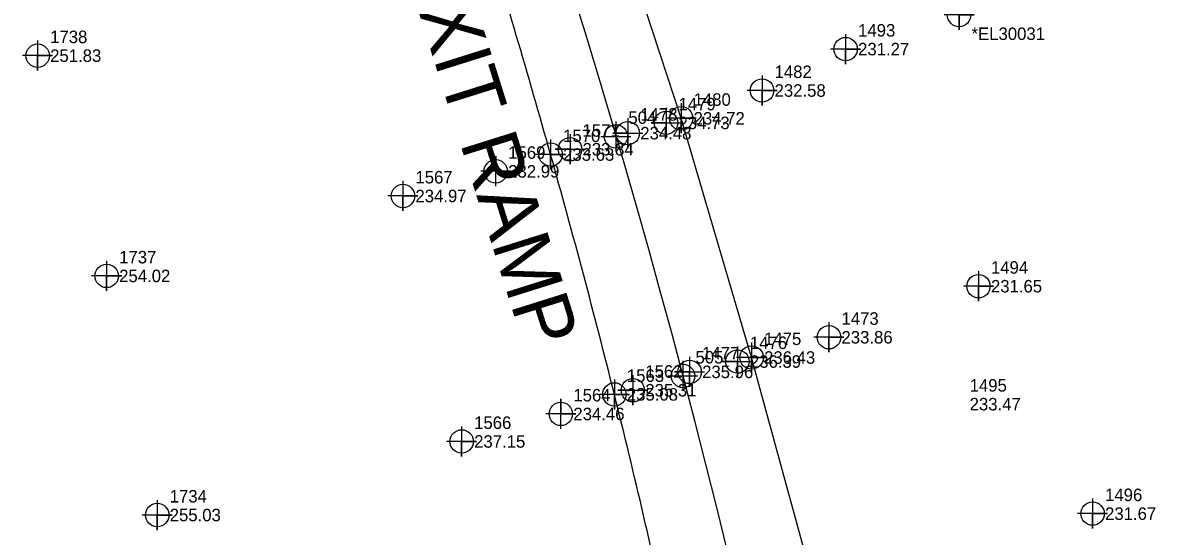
# Model space of a CAD drawing. Extents: x 2130621 to 2131998, y 642516 to 644503.
# Drawn here: x 2131046.3 to 2131272.8, y 643731.5 to 643834.2 of the extents above; entities that cross this region are included whole.
import ezdxf

# ---------------------------------------------------------------- set-up
doc = ezdxf.new("R2010")
doc.units = 0
for name, color, linetype in [('Cogo Default Point CELL', 7, 'Continuous'), ('COGO Default Point Number', 7, 'Continuous'), ('Exist Other Culture Area Outline Cogo Elevation', 7, 'Continuous'), ('Exist Other Culture Area Outline Cogo Number', 7, 'Continuous'), ('Exist Other Culture Area Outline Cogo Point CELL', 7, 'Continuous'), ('Exist Other Culture Fence Line Cogo Elevation', 7, 'Continuous'), ('Exist Other Culture Fence Line Cogo Number', 7, 'Continuous'), ('Exist Other Culture Fence Line Cogo Point CELL', 7, 'Continuous'), ('Exist Roads EOP', 7, 'Continuous'), ('Exist Roads EOP Cogo Elevation', 7, 'Continuous'), ('Exist Roads EOP Cogo Number', 7, 'Continuous'), ('Exist Roads EOP Cogo Point CELL', 7, 'Continuous'), ('Exist Roads EOP Other Cogo Comment', 7, 'Continuous'), ('Exist Roads EOP Other Cogo Point CELL', 7, 'Continuous'), ('Exist Roads EOT Cogo Elevation', 7, 'Continuous'), ('Exist Roads EOT Cogo Number', 7, 'Continuous'), ('Exist Roads EOT Cogo Point CELL', 7, 'Continuous'), ('Exist Roads EOT Text', 7, 'Continuous'), ('Exist Roads Soil Cogo Elevation', 7, 'Continuous'), ('Exist Roads Soil Cogo Number', 7, 'Continuous'), ('Exist Roads Soil Cogo Point CELL', 7, 'Continuous'), ('Exist Vegetation Tree Cogo Elevation', 7, 'Continuous'), ('Exist Vegetation Tree Cogo Number', 7, 'Continuous'), ('Exist Vegetation Woods Line Cogo Elevation', 7, 'Continuous'), ('Exist Vegetation Woods Line Cogo Number', 7, 'Continuous'), ('Exist Vegetation Woods Line Cogo Point CELL', 7, 'Continuous'), ('Prop Horizontal Alignment', 7, 'Continuous')]:
    doc.layers.add(name, color=color, linetype=linetype)

msp = doc.modelspace()

# ---------------------------------------------------------------- linework, layer by layer
at = {"layer": 'Cogo Default Point CELL'}
for points in [[(2131164.92, 643814.47), (2131164.92, 643811.47)], [(2131161.92, 643811.47), (2131164.92, 643811.47)], [(2131164.92, 643811.47), (2131167.92, 643811.47)], [(2131164.92, 643811.47), (2131164.92, 643808.47)], [(2131178.34, 643766.57), (2131178.34, 643763.57)], [(2131175.34, 643763.57), (2131178.34, 643763.57)], [(2131178.34, 643763.57), (2131181.34, 643763.57)], [(2131178.34, 643763.57), (2131178.34, 643760.57)]]:
    msp.add_lwpolyline(points, dxfattribs=at)
for centre in [(2131164.92, 643811.47), (2131178.34, 643763.57)]:
    msp.add_circle(centre, 2.34, dxfattribs=at)
at = {"layer": 'Exist Other Culture Area Outline Cogo Point CELL'}
for points in [[(2131210.86, 643831.93), (2131210.86, 643825.93), (2131210.86, 643828.93), (2131213.86, 643828.93), (2131207.86, 643828.93)], [(2131194.16, 643823.65), (2131194.16, 643817.65), (2131194.16, 643820.65), (2131197.16, 643820.65), (2131191.16, 643820.65)], [(2131237.43, 643784.52), (2131237.43, 643778.52), (2131237.43, 643781.52), (2131240.43, 643781.52), (2131234.43, 643781.52)], [(2131207.54, 643774.31), (2131207.54, 643768.31), (2131207.54, 643771.31), (2131210.54, 643771.31), (2131204.54, 643771.31)], [(2131260.25, 643739.05), (2131260.25, 643733.05), (2131260.25, 643736.05), (2131263.25, 643736.05), (2131257.25, 643736.05)]]:
    msp.add_lwpolyline(points, dxfattribs=at)
for centre in [(2131210.86, 643828.93), (2131194.16, 643820.65), (2131237.43, 643781.52), (2131207.54, 643771.31), (2131260.25, 643736.05)]:
    msp.add_circle(centre, 2.34, dxfattribs=at)
at = {"layer": 'Exist Other Culture Fence Line Cogo Point CELL'}
for points in [[(2131049.29, 643830.62), (2131049.29, 643824.62), (2131049.29, 643827.62), (2131052.29, 643827.62), (2131046.29, 643827.62)], [(2131063.09, 643786.58), (2131063.09, 643780.58), (2131063.09, 643783.58), (2131066.09, 643783.58), (2131060.09, 643783.58)], [(2131073.2, 643738.77), (2131073.2, 643732.77), (2131073.2, 643735.77), (2131076.2, 643735.77), (2131070.2, 643735.77)]]:
    msp.add_lwpolyline(points, dxfattribs=at)
for centre in [(2131049.29, 643827.62), (2131063.09, 643783.58), (2131073.2, 643735.77)]:
    msp.add_circle(centre, 2.34, dxfattribs=at)
at = {"layer": 'Exist Roads EOP'}
msp.add_lwpolyline([(2131264.27, 643222.56), (2131259.88, 643269.33), (2131257.02, 643319.4), (2131254.26, 643369.65), (2131250.08, 643419.42), (2131246.15, 643469.03), (2131240.84, 643519.13), (2131234.37, 643568.56), (2131226.33, 643620.18), (2131217.03, 643668.71), (2131205.62, 643717.61), (2131192.06, 643767.26), (2131177.97, 643815.09), (2131162.29, 643862.93), (2131145.36, 643910.85), (2131126.91, 643957.29), (2131112.37, 643996.12)], dxfattribs=at)
msp.add_spline([(2131166.25, 643216.7), (2131171.81, 643218.72), (2131182.37, 643223.97), (2131191.81, 643231.15), (2131200.5, 643239.7), (2131208.81, 643249.07), (2131216.07, 643259), (2131218.72, 643264.35), (2131220.54, 643270.1), (2131222.84, 643282.01), (2131224.36, 643293.92), (2131224.88, 643317.79), (2131222.06, 643367.67), (2131218.54, 643416.81), (2131214.32, 643466.35), (2131209.17, 643515.67), (2131202.79, 643565.15), (2131195.05, 643613.99), (2131186.4, 643662.48), (2131176.01, 643711.41), (2131164.62, 643759.89), (2131151.87, 643807.85), (2131137.86, 643855.41), (2131122.57, 643902.86), (2131105.96, 643949.49), (2131091.53, 643988.04)], degree=3, dxfattribs=at)
at = {"layer": 'Exist Roads EOP Cogo Point CELL'}
for points in [[(2131177.97, 643818.09), (2131177.97, 643812.09), (2131177.97, 643815.09), (2131180.97, 643815.09), (2131174.97, 643815.09)], [(2131151.87, 643810.85), (2131151.87, 643804.85), (2131151.87, 643807.85), (2131154.87, 643807.85), (2131148.87, 643807.85)], [(2131192.06, 643770.26), (2131192.06, 643764.26), (2131192.06, 643767.26), (2131195.06, 643767.26), (2131189.06, 643767.26)], [(2131164.62, 643762.89), (2131164.62, 643756.89), (2131164.62, 643759.89), (2131167.62, 643759.89), (2131161.62, 643759.89)]]:
    msp.add_lwpolyline(points, dxfattribs=at)
for centre in [(2131177.97, 643815.09), (2131151.87, 643807.85), (2131192.06, 643767.26), (2131164.62, 643759.89)]:
    msp.add_circle(centre, 2.34, dxfattribs=at)
at = {"layer": 'Exist Roads EOP Other Cogo Point CELL'}
msp.add_lwpolyline([(2131233.55, 643838.75), (2131233.55, 643832.75), (2131233.55, 643835.75), (2131236.55, 643835.75), (2131230.55, 643835.75)], dxfattribs=at)
msp.add_circle((2131233.55, 643835.75), 2.34, dxfattribs=at)
at = {"layer": 'Exist Roads EOT Cogo Point CELL'}
for points in [[(2131167.3, 643815.12), (2131167.3, 643809.12), (2131167.3, 643812.12), (2131164.3, 643812.12), (2131170.3, 643812.12)], [(2131174.95, 643817.18), (2131174.95, 643811.18), (2131174.95, 643814.18), (2131171.95, 643814.18), (2131177.95, 643814.18)], [(2131155.75, 643811.91), (2131155.75, 643805.91), (2131155.75, 643808.91), (2131152.75, 643808.91), (2131158.75, 643808.91)], [(2131189.23, 643769.46), (2131189.23, 643763.46), (2131189.23, 643766.46), (2131186.23, 643766.46), (2131192.23, 643766.46)], [(2131179.67, 643767.39), (2131179.67, 643761.39), (2131179.67, 643764.39), (2131176.67, 643764.39), (2131182.67, 643764.39)], [(2131168.31, 643763.72), (2131168.31, 643757.72), (2131168.31, 643760.72), (2131165.31, 643760.72), (2131171.31, 643760.72)]]:
    msp.add_lwpolyline(points, dxfattribs=at)
for centre in [(2131174.95, 643814.18), (2131167.3, 643812.12), (2131155.75, 643808.91), (2131189.23, 643766.46), (2131179.67, 643764.39), (2131168.31, 643760.72)]:
    msp.add_circle(centre, 2.34, dxfattribs=at)
at = {"layer": 'Exist Roads Soil Cogo Point CELL'}
for points in [[(2131140.89, 643801.49), (2131140.89, 643807.49), (2131140.89, 643804.49), (2131143.89, 643804.49), (2131137.89, 643804.49)], [(2131153.92, 643752.98), (2131153.92, 643758.98), (2131153.92, 643755.98), (2131156.92, 643755.98), (2131150.92, 643755.98)]]:
    msp.add_lwpolyline(points, dxfattribs=at)
for centre in [(2131140.89, 643804.49), (2131153.92, 643755.98)]:
    msp.add_circle(centre, 2.34, dxfattribs=at)
at = {"layer": 'Exist Vegetation Woods Line Cogo Point CELL'}
for points in [[(2131122.34, 643802.56), (2131122.34, 643796.56), (2131122.34, 643799.56), (2131125.34, 643799.56), (2131119.34, 643799.56)], [(2131134.08, 643753.48), (2131134.08, 643747.48), (2131134.08, 643750.48), (2131137.08, 643750.48), (2131131.08, 643750.48)]]:
    msp.add_lwpolyline(points, dxfattribs=at)
for centre in [(2131122.34, 643799.56), (2131134.08, 643750.48)]:
    msp.add_circle(centre, 2.34, dxfattribs=at)
at = {"layer": 'Prop Horizontal Alignment'}
msp.add_arc((2129448.47, 643307.66), 1788.96, 4.14306, 22.49968, dxfattribs=at)

# ---------------------------------------------------------------- texts
at = {"layer": 'COGO Default Point Number'}
for s, p in [('504', (2131167.42, 643813.97)), ('505', (2131180.84, 643766.07))]:
    msp.add_text(s, height=2.5, dxfattribs=at).set_placement(p)
at = {"layer": 'Exist Other Culture Area Outline Cogo Elevation'}
for s, p in [('231.27', (2131213.36, 643827.68)), ('232.58', (2131196.66, 643819.4)), ('231.65', (2131239.93, 643780.27)), ('233.86', (2131210.04, 643770.06)), ('231.67', (2131262.75, 643734.8))]:
    msp.add_text(s, height=2.5, dxfattribs=at).set_placement(p)
at = {"layer": 'Exist Other Culture Area Outline Cogo Number'}
for s, p in [('1493', (2131213.36, 643831.43)), ('1482', (2131196.66, 643823.15)), ('1494', (2131239.93, 643784.02)), ('1473', (2131210.04, 643773.81)), ('1496', (2131262.75, 643738.55))]:
    msp.add_text(s, height=2.5, dxfattribs=at).set_placement(p)
at = {"layer": 'Exist Other Culture Fence Line Cogo Elevation'}
for s, p in [('251.83', (2131051.79, 643826.37)), ('254.02', (2131065.59, 643782.33)), ('255.03', (2131075.7, 643734.52))]:
    msp.add_text(s, height=2.5, dxfattribs=at).set_placement(p)
at = {"layer": 'Exist Other Culture Fence Line Cogo Number'}
for s, p in [('1738', (2131051.79, 643830.12)), ('1737', (2131065.59, 643786.08)), ('1734', (2131075.7, 643738.27))]:
    msp.add_text(s, height=2.5, dxfattribs=at).set_placement(p)
at = {"layer": 'Exist Roads EOP Cogo Elevation'}
for s, p in [('234.72', (2131180.47, 643813.84)), ('233.63', (2131154.37, 643806.6)), ('236.43', (2131194.56, 643766.01)), ('235.08', (2131167.12, 643758.64))]:
    msp.add_text(s, height=2.5, dxfattribs=at).set_placement(p)
at = {"layer": 'Exist Roads EOP Cogo Number'}
for s, p in [('1480', (2131180.47, 643817.59)), ('1570', (2131154.37, 643810.35)), ('1475', (2131194.56, 643769.76)), ('1563', (2131167.12, 643762.39))]:
    msp.add_text(s, height=2.5, dxfattribs=at).set_placement(p)
at = {"layer": 'Exist Roads EOP Other Cogo Comment'}
msp.add_text('*EL30031', height=2.5, dxfattribs=at).set_placement((2131236.05, 643830.75))
at = {"layer": 'Exist Roads EOT Cogo Elevation'}
for s, p in [('234.73', (2131177.45, 643812.93)), ('234.48', (2131169.8, 643810.87)), ('233.84', (2131158.25, 643807.66)), ('236.39', (2131191.73, 643765.21)), ('235.96', (2131182.17, 643763.14)), ('235.31', (2131170.81, 643759.47))]:
    msp.add_text(s, height=2.5, dxfattribs=at).set_placement(p)
at = {"layer": 'Exist Roads EOT Cogo Number'}
for s, p in [('1479', (2131177.45, 643816.68)), ('1478', (2131169.8, 643814.62)), ('1571', (2131158.25, 643811.41)), ('1476', (2131191.73, 643768.96)), ('1477', (2131182.17, 643766.89)), ('1562', (2131170.81, 643763.22))]:
    msp.add_text(s, height=2.5, dxfattribs=at).set_placement(p)
at = {"layer": 'Exist Roads EOT Text'}
msp.add_text('I-40 EAST BOUND EXIT RAMP', height=11.3735, rotation=287.4395, dxfattribs=at).set_placement((2131082.27, 643973.9))
at = {"layer": 'Exist Roads Soil Cogo Elevation'}
for s, p in [('232.99', (2131143.39, 643803.24)), ('234.46', (2131156.42, 643754.73))]:
    msp.add_text(s, height=2.5, dxfattribs=at).set_placement(p)
at = {"layer": 'Exist Roads Soil Cogo Number'}
for s, p in [('1569', (2131143.39, 643806.99)), ('1564', (2131156.42, 643758.48))]:
    msp.add_text(s, height=2.5, dxfattribs=at).set_placement(p)
at = {"layer": 'Exist Vegetation Tree Cogo Elevation'}
msp.add_text('233.47', height=2.5, dxfattribs=at).set_placement((2131235.67, 643756.69))
at = {"layer": 'Exist Vegetation Tree Cogo Number'}
msp.add_text('1495', height=2.5, dxfattribs=at).set_placement((2131235.67, 643760.44))
at = {"layer": 'Exist Vegetation Woods Line Cogo Elevation'}
for s, p in [('234.97', (2131124.84, 643798.31)), ('237.15', (2131136.58, 643749.23))]:
    msp.add_text(s, height=2.5, dxfattribs=at).set_placement(p)
at = {"layer": 'Exist Vegetation Woods Line Cogo Number'}
for s, p in [('1567', (2131124.84, 643802.06)), ('1566', (2131136.58, 643752.98))]:
    msp.add_text(s, height=2.5, dxfattribs=at).set_placement(p)

doc.saveas('drawing.dxf')
